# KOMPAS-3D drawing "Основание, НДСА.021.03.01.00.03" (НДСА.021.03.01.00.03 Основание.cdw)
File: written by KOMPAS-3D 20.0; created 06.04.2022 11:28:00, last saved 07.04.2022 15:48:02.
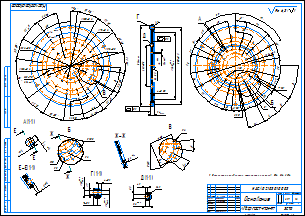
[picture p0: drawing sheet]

Sheet 1: A2, landscape

Document properties: Автор: 111; PLM_CDWXDTO: <item xmlns="http://appius.ru/pdm" xmlns:xs="http://www.w3.org/2001/XMLSchema" xmlns:xsi="http://www.w3.org/2001/XMLSchema-instance" xsi:type="item">  <element xmlns:d2p1="http://v8.1c.ru/8.1/data/enterprise/current-config" xsi:type="d2p1:CatalogRef.aps_Элемен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; Масса: 2.19; Знак неуказанной шероховатости: 4; Параметр неуказанной шероховатости: Ra 6,3; 210460669933: <item xmlns="http://appius.ru/pdm" xmlns:xs="http://www.w3.org/2001/XMLSchema" xmlns:xsi="http://www.w3.org/2001/XMLSchema-instance" xsi:type="item">  <element xmlns:d2p1="http://v8.1c.ru/8.1/data/enterprise/current-config" xsi:type="d2p1:CatalogRef.aps_Элемен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; 210460670033: <item xmlns="http://appius.ru/pdm" xmlns:xs="http://www.w3.org/2001/XMLSchema" xmlns:xsi="http://www.w3.org/2001/XMLSchema-instance" xsi:type="item">  <element xmlns:d2p1="http://v8.1c.ru/8.1/data/enterprise/current-config" xsi:type="d2p1:CatalogRef.aps_Элемен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; PDM_DOCXDTO: <item xmlns="http://appius.ru/pdm" xmlns:xs="http://www.w3.org/2001/XMLSchema" xmlns:xsi="http://www.w3.org/2001/XMLSchema-instance" xsi:type="item">  <element xmlns:d2p1="http://v8.1c.ru/8.1/data/enterprise/current-config" xsi:type="d2p1:CatalogRef.aps_Элемен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; PDM_ITEMXDTO: <item xmlns="http://appius.ru/pdm" xmlns:xs="http://www.w3.org/2001/XMLSchema" xmlns:xsi="http://www.w3.org/2001/XMLSchema-instance" xsi:type="item">  <element xmlns:d2p1="http://v8.1c.ru/8.1/data/enterprise/current-config" xsi:type="d2p1:CatalogRef.aps_Элемен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; PDM_DRAWINGXDTO: <item xmlns="http://appius.ru/pdm" xmlns:xs="http://www.w3.org/2001/XMLSchema" xmlns:xsi="http://www.w3.org/2001/XMLSchema-instance" xsi:type="item">  <element xmlns:d2p1="http://v8.1c.ru/8.1/data/enterprise/current-config" xsi:type="d2p1:CatalogRef.aps_Элемен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

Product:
- Part/product: Основание  | designation НДСА.021.03.01.00.03
    Материал: АМг2,5 ГОСТ 4784-97 (density 2680 kg/m3)
    Масса: 2.18949
    additional columns: <item xmlns="http://appius.ru/pdm" xmlns:xs="http://www.w3.org/2001/XMLSchema" x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; <item xmlns="http://appius.ru/pdm" xmlns:xs="http://www.w3.org/2001/XMLSchema" x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; <item xmlns="http://appius.ru/pdm" xmlns:xs="http://www.w3.org/2001/XMLSchema" x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; <item xmlns="http://appius.ru/pdm" xmlns:xs="http://www.w3.org/2001/XMLSchema" x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; <item xmlns="http://appius.ru/pdm" xmlns:xs="http://www.w3.org/2001/XMLSchema" x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
    source file: НДСА.021.03.01.00.03 Основание.cdw

Title block, sheet 1: Наименование: Основание; designation: НДСА.021.03.01.00.03; Материал: АМг2,5 ГОСТ 4784-97; Масса: 2,19; Количество листов документа: 1; organisation: ЭСТО; Форматы листов документа: A2; stored path: C:\Users\s.pischagina\Desktop\PLM\НДСА.021.03.01.00.03 Основание.cdw; Разработал: Пищагина; Проверил: Белецкий; Утвердил: Виноградов; Разработал, date: 07.04.22

Views: Вид 1, Сверху, Проекционный вид 2, Местный разрез 1, Выносной элемент 4, Разрез Б-Б, Выносной элемент 6, Разрез Г-Г, Выносной элемент 8, Выносной элемент 9, Выносной элемент 10, Выносной элемент А, Выносной элемент, Разрез Е-Е, Выносной элемент Б, Разрез Ж-Ж, Выносной элемент В, Выносной элемент Г, Выносной элемент Д
Referenced files in C:\Users\s.pischagina\Desktop\PLM\: НДСА.021.03.01.00.03 Основание.m3d
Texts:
  Ra 3,2
  Ra 6,3
  Ra 6,3 ( )
  НДСА.021.03.01.00.03 Основание
Dimensions and other numbers on the sheet: 7 30'; 22 30'; 72±0,2; 100±0,2; 102±0,2; 132±0,5; 192±0,5; 4; 3отв; -7Н; 5; 28отв; 260; 300±0,2; 162±0,3; 316; 3; 14; 0.1; 6; 21отв; 12,2; 4,1; 105; 10; 2; 8,2; 90; 96; 7±0,1; 8; 1:2; 1; 2,19; 07.04.22

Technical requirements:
  Неуказанные предельные отклонения размеров: H14, h14, JS14.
